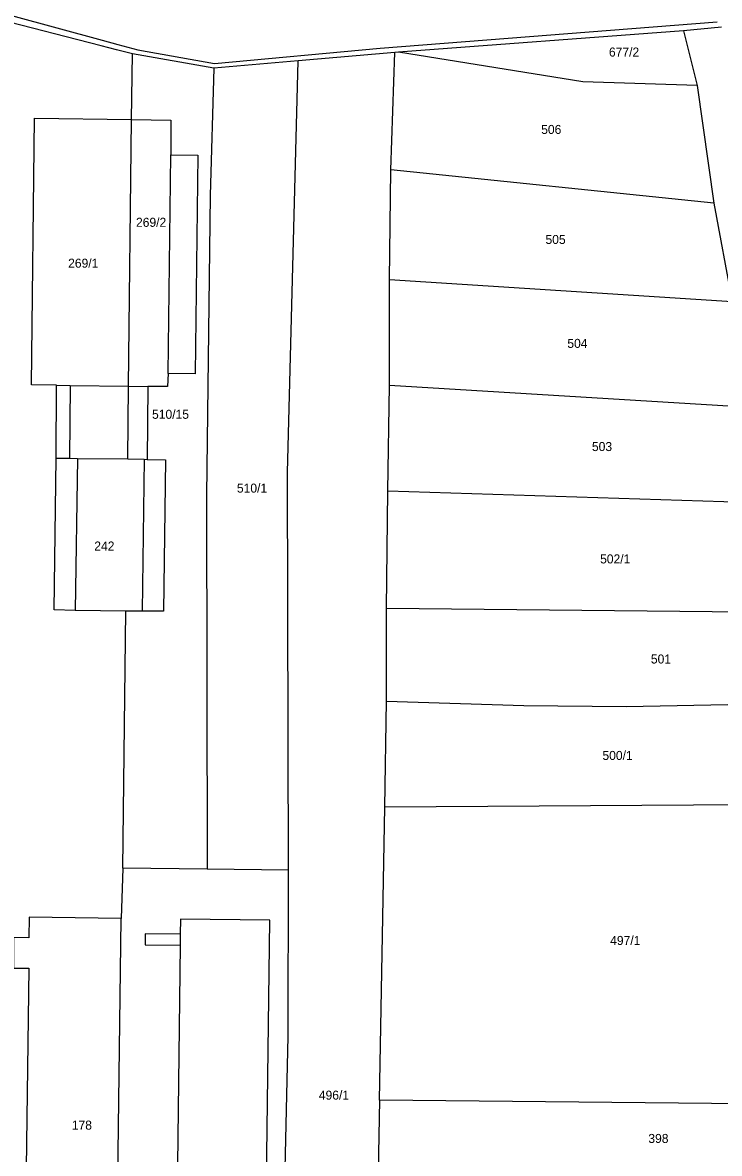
# Model space of a CAD drawing. Extents: x -747333 to -743907, y -1134120 to -1130051.
# Drawn here: x -746462.8 to -746331.7, y -1132539.7 to -1132327 of the extents above; entities that cross this region are included whole.
import ezdxf

# ---------------------------------------------------------------- set-up
doc = ezdxf.new("R2010")
doc.units = 0
for name, color, linetype in [('Hranice parcel', 7, 'Continuous'), ('Parcelní čísla', 7, 'Continuous'), ('Vnitřní kresba', 7, 'Continuous')]:
    doc.layers.add(name, color=color, linetype=linetype)

msp = doc.modelspace()

# ---------------------------------------------------------------- linework, layer by layer
at = {"layer": 'Hranice parcel'}
for p, q in [((-746448.07, -1132331.38), (-746487.88, -1132321.09)), ((-746331.35, -1132327.82), (-746338.47, -1132328.52)), ((-746338.47, -1132328.52), (-746392.12, -1132332.53)), ((-746338.47, -1132328.52), (-746335.9, -1132338.8)), ((-746445.16, -1132332.13), (-746448.07, -1132331.38)), ((-746442.17, -1132332.88), (-746445.16, -1132332.13)), ((-746392.82, -1132332.59), (-746411.01, -1132334.18)), ((-746393.53, -1132354.71), (-746392.82, -1132332.59)), ((-746392.12, -1132332.53), (-746392.82, -1132332.59)), ((-746442.31, -1132345.22), (-746442.17, -1132332.88)), ((-746426.85, -1132335.55), (-746442.17, -1132332.88)), ((-746411.01, -1132334.18), (-746426.85, -1132335.55)), ((-746335.9, -1132338.8), (-746332.76, -1132360.93)), ((-746460.56, -1132344.98), (-746442.31, -1132345.22)), ((-746442.31, -1132345.22), (-746434.93, -1132345.32)), ((-746393.81, -1132375.41), (-746393.53, -1132354.71)), ((-746332.76, -1132360.93), (-746393.53, -1132354.71)), ((-746332.76, -1132360.93), (-746329.31, -1132379.55)), ((-746329.31, -1132379.55), (-746393.81, -1132375.41)), ((-746393.81, -1132395.25), (-746393.81, -1132375.41)), ((-746394.09, -1132415.09), (-746393.81, -1132395.25)), ((-746319.27, -1132399.8), (-746393.81, -1132395.25)), ((-746452.53, -1132408.97), (-746443.06, -1132409.09)), ((-746443.06, -1132409.09), (-746439.94, -1132409.14)), ((-746439.94, -1132409.14), (-746439.38, -1132409.16)), ((-746394.38, -1132437.22), (-746394.09, -1132415.09)), ((-746394.09, -1132415.09), (-746307.32, -1132417.87)), ((-746443.39, -1132437.7), (-746452.91, -1132437.58)), ((-746443.96, -1132486.07), (-746443.39, -1132437.7)), ((-746440.33, -1132437.74), (-746443.39, -1132437.7)), ((-746394.38, -1132454.63), (-746394.38, -1132437.22)), ((-746306.63, -1132438.08), (-746394.38, -1132437.22)), ((-746394.67, -1132474.61), (-746394.38, -1132454.63)), ((-746349.28, -1132455.63), (-746306.06, -1132454.82)), ((-746395.66, -1132529.71), (-746394.67, -1132474.61)), ((-746305.4, -1132474), (-746394.67, -1132474.61)), ((-746443.96, -1132486.07), (-746444.3, -1132495.53)), ((-746428.08, -1132486.27), (-746443.96, -1132486.07)), ((-746412.82, -1132486.47), (-746428.08, -1132486.27)), ((-746445.35, -1132580.44), (-746444.3, -1132495.53)), ((-746395.66, -1132529.71), (-746395.95, -1132543.13)), ((-746303.46, -1132530.68), (-746395.66, -1132529.71))]:
    msp.add_line(p, q, dxfattribs=at)
for points in [[(-746335.9, -1132338.8), (-746357.42, -1132338.16), (-746392.12, -1132332.53)], [(-746412.82, -1132486.47), (-746413.02, -1132411.65), (-746411.01, -1132334.18)], [(-746426.85, -1132335.55), (-746427.53, -1132359.53), (-746428.24, -1132415.89), (-746428.08, -1132486.27)], [(-746456.52, -1132408.91), (-746456.45, -1132395.21), (-746461.15, -1132395.16), (-746460.56, -1132344.98)], [(-746443.06, -1132409.09), (-746442.9, -1132395.38), (-746442.31, -1132345.22)], [(-746434.93, -1132345.32), (-746434.96, -1132351.85), (-746429.89, -1132351.96), (-746430.39, -1132393.08), (-746435.47, -1132393.02), (-746435.54, -1132395.46), (-746439.24, -1132395.43), (-746439.38, -1132409.16)], [(-746452.91, -1132437.58), (-746456.87, -1132437.46), (-746456.52, -1132408.91)], [(-746456.52, -1132408.91), (-746453.98, -1132408.95), (-746452.53, -1132408.97)], [(-746439.38, -1132409.16), (-746435.95, -1132409.27), (-746436.34, -1132437.75), (-746440.33, -1132437.74)], [(-746394.38, -1132454.63), (-746368.55, -1132455.49), (-746349.28, -1132455.63)], [(-746415.02, -1132611.93), (-746412.87, -1132517.7), (-746412.82, -1132486.47)], [(-746444.3, -1132495.53), (-746461.6, -1132495.32), (-746461.63, -1132499.17), (-746464.54, -1132499.14), (-746464.56, -1132504.89), (-746461.68, -1132504.91), (-746462.63, -1132580.24), (-746445.35, -1132580.44)], [(-746433.2, -1132500.57), (-746434.38, -1132598.64), (-746417.62, -1132598.8), (-746416.34, -1132495.88), (-746433.14, -1132495.69), (-746433.17, -1132498.48), (-746439.8, -1132498.4), (-746439.79, -1132500.49), (-746433.2, -1132500.57)]]:
    msp.add_lwpolyline(points, dxfattribs=at)
at = {"layer": 'Vnitřní kresba'}
for p, q in [((-746464.89, -1132325.65), (-746447.83, -1132330.31)), ((-746395.58, -1132331.79), (-746332.14, -1132326.83)), ((-746447.83, -1132330.31), (-746444.93, -1132331.1)), ((-746444.93, -1132331.1), (-746441.17, -1132332.13)), ((-746441.17, -1132332.13), (-746426.75, -1132334.69)), ((-746426.75, -1132334.69), (-746395.58, -1132331.79)), ((-746435.47, -1132393.02), (-746434.96, -1132351.85)), ((-746456.45, -1132395.21), (-746453.88, -1132395.24)), ((-746453.88, -1132395.24), (-746453.98, -1132408.95)), ((-746453.88, -1132395.24), (-746442.9, -1132395.38)), ((-746442.9, -1132395.38), (-746439.24, -1132395.43)), ((-746452.53, -1132408.97), (-746452.91, -1132437.58)), ((-746439.94, -1132409.14), (-746440.33, -1132437.74)), ((-746433.17, -1132498.48), (-746433.2, -1132500.57))]:
    msp.add_line(p, q, dxfattribs=at)

# ---------------------------------------------------------------- texts
at = {"layer": 'Parcelní čísla'}
for s, p in [('677/2', (-746352.52, -1132333.38)), ('506', (-746365.27, -1132347.94)), ('269/2', (-746441.493, -1132365.41)), ('505', (-746364.46, -1132368.64)), ('269/1', (-746454.263, -1132373.1)), ('504', (-746360.35, -1132388.19)), ('510/15', (-746438.475, -1132401.53)), ('503', (-746355.72, -1132407.6)), ('510/1', (-746422.51, -1132415.42)), ('242', (-746449.344, -1132426.32)), ('502/1', (-746354.183, -1132428.74)), ('501', (-746344.63, -1132447.57)), ('500/1', (-746353.743, -1132465.72)), ('497/1', (-746352.293, -1132500.53)), ('496/1', (-746407.1, -1132529.63)), ('178', (-746453.57, -1132535.27)), ('398', (-746345.11, -1132537.78))]:
    msp.add_text(s, height=1.7, dxfattribs=at).set_placement(p)

doc.saveas('drawing.dxf')
